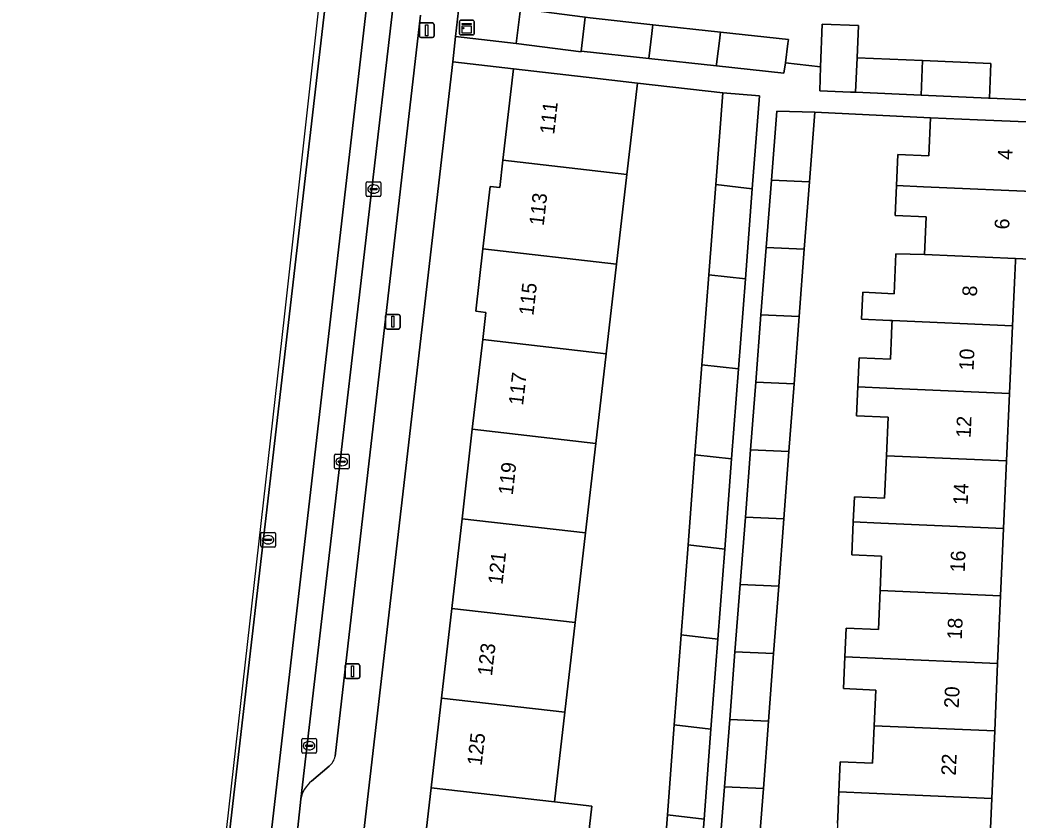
# Model space of a CAD drawing. Extents: x 162250 to 162661, y 380743 to 381606.
# Drawn here: x 162268.3 to 162336.5, y 381046.9 to 381101.5 of the extents above; entities that cross this region are included whole.
import ezdxf

# ---------------------------------------------------------------- set-up
doc = ezdxf.new("R2010")
doc.units = 0
for name, color, linetype in [('IMGEO_Erf', 7, 'Continuous'), ('IMGEO_Kast', 7, 'Continuous'), ('IMGEO_Kolk', 7, 'Continuous'), ('IMGEO_Lichtmast', 7, 'Continuous'), ('IMGEO_Pand', 7, 'Continuous'), ('IMGEO_Pand_nummerreeks', 7, 'Continuous'), ('IMGEO_Parkeervlak_open', 7, 'Continuous'), ('IMGEO_Rijbaan_lokaal_gesloten', 7, 'Continuous'), ('IMGEO_Rioolput', 7, 'Continuous'), ('IMGEO_Voetpad_open', 7, 'Continuous')]:
    doc.layers.add(name, color=color, linetype=linetype)

msp = doc.modelspace()

# ---------------------------------------------------------------- linework, layer by layer
at = {"layer": 'IMGEO_Erf'}
msp.add_lwpolyline([(162341.565, 381113.994), (162300.19, 381118.786), (162298.069, 381100.412), (162302.196, 381099.936), (162302.502, 381102.301), (162306.912, 381101.731), (162307.261, 381101.686), (162311.531, 381101.218), (162316.15, 381100.712), (162320.788, 381100.203), (162320.754, 381099.942), (162320.583, 381098.618), (162322.993, 381098.336), (162323.098, 381101.264), (162325.575, 381101.155), (162325.478, 381098.962), (162329.957, 381098.765), (162334.625, 381098.559), (162334.521, 381096.197), (162340.767, 381095.921)], close=True, dxfattribs=at)
for points in [[(162295.685, 381042.988), (162296.39, 381049.11), (162297.096, 381055.232), (162297.801, 381061.354), (162298.507, 381067.476), (162299.212, 381073.598), (162299.918, 381079.72), (162300.131, 381081.572), (162299.44, 381081.652), (162299.932, 381085.921), (162300.422, 381090.175), (162301.083, 381090.099), (162301.298, 381091.967), (162302.017, 381098.208), (162297.87, 381098.686), (162285.829, 380994.375)], [(162312.06, 381041.1), (162312.531, 381047.249), (162313.002, 381053.398), (162313.472, 381059.548), (162313.943, 381065.696), (162314.414, 381071.845), (162314.885, 381077.995), (162315.356, 381084.144), (162315.827, 381090.293), (162316.307, 381096.56), (162310.485, 381097.232), (162309.766, 381090.991), (162309.06, 381084.869), (162308.355, 381078.747), (162307.649, 381072.625), (162306.943, 381066.503), (162306.238, 381060.381), (162305.532, 381054.259), (162304.827, 381048.137), (162307.374, 381047.844), (162306.668, 381041.722)], [(162324.153, 381046.694), (162324.169, 381047.067), (162324.247, 381048.83), (162324.337, 381050.884), (162326.542, 381050.787), (162326.654, 381053.343), (162326.761, 381055.776), (162324.549, 381055.873), (162324.645, 381058.052), (162324.731, 381060.002), (162326.937, 381059.905), (162327.054, 381062.565), (162327.158, 381064.916), (162325.126, 381065.006), (162325.225, 381067.264), (162325.301, 381068.982), (162327.356, 381068.891), (162327.483, 381071.784), (162327.599, 381074.413), (162325.447, 381074.508), (162325.534, 381076.488), (162325.621, 381078.467), (162327.753, 381078.374), (162327.828, 381080.068), (162327.856, 381080.717), (162327.869, 381081.005), (162327.721, 381081.011), (162325.787, 381081.096), (162325.868, 381082.941), (162328.005, 381082.846), (162328.125, 381085.575), (162330.088, 381085.526), (162330.201, 381088.097), (162328.092, 381088.19), (162328.181, 381090.229), (162328.274, 381092.345), (162330.388, 381092.252), (162330.503, 381094.867), (162322.586, 381095.235), (162322.226, 381090.491), (162321.877, 381085.887), (162321.527, 381081.284), (162321.178, 381076.68), (162320.829, 381072.076), (162320.479, 381067.473), (162320.13, 381062.869), (162319.78, 381058.266), (162319.431, 381053.661), (162319.081, 381049.058), (162318.732, 381044.454)], [(162338.294, 381085.165), (162336.297, 381085.253), (162336.29, 381085.1), (162336.246, 381084.098), (162336.094, 381080.643), (162335.891, 381076.033), (162335.688, 381071.423), (162335.485, 381066.813), (162335.282, 381062.202), (162335.079, 381057.592), (162334.877, 381052.982), (162334.674, 381048.372), (162334.471, 381043.762)]]:
    msp.add_lwpolyline(points, dxfattribs=at)
at = {"layer": 'IMGEO_Kast'}
for p, q in [((162298.332, 381100.593), (162298.332, 381101.434)), ((162298.332, 381101.434), (162298.332, 381100.593)), ((162298.407, 381101.518), (162299.248, 381101.518)), ((162299.248, 381101.518), (162298.407, 381101.518)), ((162299.332, 381101.443), (162299.332, 381100.602)), ((162299.332, 381100.602), (162299.332, 381101.443)), ((162299.257, 381100.518), (162298.416, 381100.518)), ((162298.416, 381100.518), (162299.257, 381100.518))]:
    msp.add_line(p, q, dxfattribs=at)
for points in [[(162298.527, 381101.308), (162299.127, 381101.308), (162299.127, 381101.223), (162298.527, 381101.223), (162298.527, 381101.308)], [(162298.527, 381101.133), (162299.127, 381101.133), (162299.127, 381100.644), (162298.527, 381100.644), (162298.527, 381101.133)]]:
    msp.add_lwpolyline(points, dxfattribs=at)
msp.add_circle((162298.611, 381100.982), 0.0377, dxfattribs=at)
for centre, start, end in [((162298.41, 381101.44), 92.4484, 184.28452), ((162298.41, 381101.44), 92.4484, 184.28452), ((162299.254, 381101.44), 2.4484, 94.28452), ((162299.254, 381101.44), 2.4484, 94.28452), ((162298.41, 381100.596), 182.4484, 274.28452), ((162298.41, 381100.596), 182.4484, 274.28452), ((162299.254, 381100.596), 272.4484, 4.28452), ((162299.254, 381100.596), 272.4484, 4.28452)]:
    msp.add_arc(centre, 0.0779, start, end, dxfattribs=at)
at = {"layer": 'IMGEO_Kolk'}
for p, q in [((162292.047, 381090.491), (162292.899, 381090.491)), ((162291.972, 381089.565), (162291.972, 381090.417)), ((162292.231, 381089.985), (162292.231, 381089.997)), ((162292.669, 381089.948), (162292.271, 381089.948)), ((162292.274, 381090.034), (162292.672, 381090.034)), ((162292.46, 381090.271), (162292.485, 381090.271)), ((162292.715, 381089.997), (162292.715, 381089.985)), ((162292.973, 381090.417), (162292.973, 381089.565)), ((162292.899, 381089.491), (162292.047, 381089.491)), ((162292.483, 381089.711), (162292.458, 381089.711)), ((162289.794, 381070.95), (162289.794, 381071.802)), ((162289.869, 381071.876), (162290.721, 381071.876)), ((162290.096, 381071.419), (162290.494, 381071.419)), ((162290.282, 381071.656), (162290.307, 381071.656)), ((162290.795, 381071.802), (162290.795, 381070.95)), ((162290.721, 381070.876), (162289.869, 381070.876)), ((162290.053, 381071.37), (162290.053, 381071.382)), ((162290.491, 381071.333), (162290.093, 381071.333)), ((162290.305, 381071.096), (162290.28, 381071.096)), ((162290.537, 381071.382), (162290.537, 381071.37)), ((162287.561, 381051.549), (162287.561, 381052.401)), ((162287.636, 381052.475), (162288.488, 381052.475)), ((162288.562, 381052.401), (162288.562, 381051.549)), ((162287.82, 381051.969), (162287.82, 381051.981)), ((162288.258, 381051.932), (162287.86, 381051.932)), ((162287.863, 381052.018), (162288.261, 381052.018)), ((162288.072, 381051.695), (162288.047, 381051.695)), ((162288.049, 381052.255), (162288.074, 381052.255)), ((162288.304, 381051.981), (162288.304, 381051.969)), ((162288.488, 381051.475), (162287.636, 381051.475))]:
    msp.add_line(p, q, dxfattribs=at)
for points in [[(162292.047, 381090.491), (162292.899, 381090.491)], [(162291.972, 381089.565), (162291.972, 381090.417)], [(162292.973, 381090.417), (162292.973, 381089.565)], [(162292.899, 381089.491), (162292.047, 381089.491)], [(162289.794, 381070.95), (162289.794, 381071.802)], [(162289.869, 381071.876), (162290.721, 381071.876)], [(162290.795, 381071.802), (162290.795, 381070.95)], [(162290.721, 381070.876), (162289.869, 381070.876)], [(162287.561, 381051.549), (162287.561, 381052.401)], [(162287.636, 381052.475), (162288.488, 381052.475)], [(162288.562, 381052.401), (162288.562, 381051.549)], [(162288.488, 381051.475), (162287.636, 381051.475)]]:
    msp.add_lwpolyline(points, dxfattribs=at)
for centre, radius, start, end in [((162292.049, 381090.415), 0.0765, 91.55205, 178.44795), ((162292.049, 381090.415), 0.0765, 91.55205, 178.44795), ((162292.897, 381090.415), 0.0765, 1.55205, 88.44795), ((162292.897, 381090.415), 0.0765, 1.55205, 88.44795), ((162292.271, 381089.994), 0.0403, 85.87752, 175.75265), ((162292.268, 381089.984), 0.0366, 178.93798, 274.71019), ((162292.672, 381089.991), 0.043, 264.86636, 352.45326), ((162292.676, 381089.996), 0.0386, 1.73085, 96.63898), ((162292.049, 381089.567), 0.0765, 181.55205, 268.44795), ((162292.049, 381089.567), 0.0765, 181.55205, 268.44795), ((162292.897, 381089.567), 0.0765, 271.55205, 358.44795), ((162292.897, 381089.567), 0.0765, 271.55205, 358.44795), ((162289.871, 381071.8), 0.0765, 91.55205, 178.44795), ((162289.871, 381071.8), 0.0765, 91.55205, 178.44795), ((162290.093, 381071.379), 0.0403, 85.87752, 175.75265), ((162290.498, 381071.381), 0.0386, 1.73085, 96.63898), ((162290.719, 381071.8), 0.0765, 1.55205, 88.44795), ((162290.719, 381071.8), 0.0765, 1.55205, 88.44795), ((162289.871, 381070.952), 0.0765, 181.55205, 268.44795), ((162289.871, 381070.952), 0.0765, 181.55205, 268.44795), ((162290.09, 381071.369), 0.0366, 178.93798, 274.71019), ((162290.494, 381071.376), 0.043, 264.86636, 352.45326), ((162290.719, 381070.952), 0.0765, 271.55205, 358.44795), ((162290.719, 381070.952), 0.0765, 271.55205, 358.44795), ((162287.638, 381052.399), 0.0765, 91.55205, 178.44795), ((162287.638, 381052.399), 0.0765, 91.55205, 178.44795), ((162288.486, 381052.399), 0.0765, 1.55205, 88.44795), ((162288.486, 381052.399), 0.0765, 1.55205, 88.44795), ((162287.86, 381051.978), 0.0403, 85.87752, 175.75265), ((162287.857, 381051.968), 0.0366, 178.93798, 274.71019), ((162288.261, 381051.975), 0.043, 264.86636, 352.45326), ((162288.265, 381051.98), 0.0386, 1.73085, 96.63898), ((162287.638, 381051.551), 0.0765, 181.55205, 268.44795), ((162287.638, 381051.551), 0.0765, 181.55205, 268.44795), ((162288.486, 381051.551), 0.0765, 271.55205, 358.44795), ((162288.486, 381051.551), 0.0765, 271.55205, 358.44795)]:
    msp.add_arc(centre, radius, start, end, dxfattribs=at)
for centre, major_axis, ratio, start_param, end_param in [((162292.459, 381089.991), (-0.387, 0.002), 0.722429, 4.712389, 7.853982), ((162292.484, 381089.991), (-0.39, 0.002), 0.717154, 1.570796, 4.712389), ((162290.281, 381071.376), (-0.387, 0.002), 0.722429, 4.712389, 7.853982), ((162290.306, 381071.376), (-0.39, 0.002), 0.717154, 1.570796, 4.712389), ((162288.048, 381051.975), (-0.387, 0.002), 0.722429, 4.712389, 7.853982), ((162288.073, 381051.975), (-0.39, 0.002), 0.717154, 1.570796, 4.712389)]:
    msp.add_ellipse(centre, major_axis=major_axis, ratio=ratio, start_param=start_param, end_param=end_param, dxfattribs=at)
at = {"layer": 'IMGEO_Lichtmast'}
for p, q in [((162295.605, 381100.438), (162295.605, 381101.238)), ((162295.605, 381101.238), (162295.605, 381100.438)), ((162295.705, 381101.338), (162296.495, 381101.338)), ((162296.495, 381101.338), (162295.705, 381101.338)), ((162296.595, 381101.238), (162296.595, 381100.438)), ((162296.595, 381100.438), (162296.595, 381101.238)), ((162296.495, 381100.338), (162295.705, 381100.338)), ((162295.705, 381100.338), (162296.495, 381100.338)), ((162293.287, 381080.529), (162293.287, 381081.329)), ((162293.287, 381081.329), (162293.287, 381080.529)), ((162293.387, 381081.429), (162294.177, 381081.429)), ((162294.177, 381081.429), (162293.387, 381081.429)), ((162294.277, 381081.329), (162294.277, 381080.529)), ((162294.277, 381080.529), (162294.277, 381081.329)), ((162294.177, 381080.429), (162293.387, 381080.429)), ((162293.387, 381080.429), (162294.177, 381080.429)), ((162290.531, 381056.662), (162290.531, 381057.462)), ((162290.531, 381057.462), (162290.531, 381056.662)), ((162290.631, 381057.562), (162291.421, 381057.562)), ((162291.421, 381057.562), (162290.631, 381057.562)), ((162291.521, 381057.462), (162291.521, 381056.662)), ((162291.521, 381056.662), (162291.521, 381057.462)), ((162291.421, 381056.562), (162290.631, 381056.562)), ((162290.631, 381056.562), (162291.421, 381056.562))]:
    msp.add_line(p, q, dxfattribs=at)
for points in [[(162296.025, 381101.213), (162296.175, 381101.213), (162296.175, 381100.463), (162296.025, 381100.463), (162296.025, 381101.213)], [(162293.707, 381081.304), (162293.857, 381081.304), (162293.857, 381080.554), (162293.707, 381080.554), (162293.707, 381081.304)], [(162290.951, 381057.437), (162291.101, 381057.437), (162291.101, 381056.687), (162290.951, 381056.687), (162290.951, 381057.437)]]:
    msp.add_lwpolyline(points, dxfattribs=at)
for centre, start, end in [((162295.705, 381101.238), 90, 180), ((162295.705, 381101.238), 90, 180), ((162296.495, 381101.238), 0, 90), ((162296.495, 381101.238), 360, 90), ((162295.705, 381100.438), 180, 270), ((162295.705, 381100.438), 180, 270), ((162296.495, 381100.438), 270, 0), ((162296.495, 381100.438), 270, 0), ((162293.387, 381081.329), 90, 180), ((162293.387, 381081.329), 90, 180), ((162294.177, 381081.329), 0, 90), ((162294.177, 381081.329), 360, 90), ((162293.387, 381080.529), 180, 270), ((162293.387, 381080.529), 180, 270), ((162294.177, 381080.529), 270, 0), ((162294.177, 381080.529), 270, 0), ((162290.631, 381057.462), 90, 180), ((162290.631, 381057.462), 90, 180), ((162291.421, 381057.462), 0, 90), ((162291.421, 381057.462), 360, 90), ((162290.631, 381056.662), 180, 270), ((162290.631, 381056.662), 180, 270), ((162291.421, 381056.662), 270, 0), ((162291.421, 381056.662), 270, 0)]:
    msp.add_arc(centre, 0.1, start, end, dxfattribs=at)
at = {"layer": 'IMGEO_Pand'}
for points in [[(162306.912, 381101.731), (162302.502, 381102.301), (162302.196, 381099.936), (162306.634, 381099.362), (162306.641, 381099.418)], [(162311.531, 381101.218), (162307.261, 381101.686), (162306.912, 381101.731), (162306.641, 381099.418), (162311.26, 381098.913), (162311.46, 381100.618), (162311.508, 381101.021)], [(162316.15, 381100.712), (162311.531, 381101.218), (162311.508, 381101.021), (162311.46, 381100.618), (162311.26, 381098.913), (162315.88, 381098.407), (162315.893, 381098.517), (162316.101, 381100.295), (162316.13, 381100.54)], [(162316.15, 381100.712), (162316.13, 381100.54), (162316.101, 381100.295), (162315.893, 381098.517), (162315.88, 381098.407), (162320.49, 381097.901), (162320.583, 381098.618), (162320.754, 381099.942), (162320.788, 381100.203)], [(162325.575, 381101.155), (162323.098, 381101.264), (162322.993, 381098.336), (162322.934, 381096.707), (162325.027, 381096.615), (162325.374, 381096.6), (162325.478, 381098.962)], [(162329.957, 381098.765), (162325.478, 381098.962), (162325.374, 381096.6), (162329.853, 381096.402)], [(162334.625, 381098.559), (162329.957, 381098.765), (162329.853, 381096.402), (162334.463, 381096.199), (162334.521, 381096.197)], [(162309.766, 381090.991), (162310.485, 381097.232), (162306.985, 381097.635), (162302.017, 381098.208), (162301.298, 381091.967)], [(162315.827, 381090.293), (162318.328, 381090.005), (162318.815, 381096.367), (162316.307, 381096.56)], [(162319.633, 381090.605), (162322.226, 381090.491), (162322.586, 381095.235), (162319.997, 381095.302)], [(162338.497, 381089.775), (162338.705, 381094.506), (162333.71, 381094.726), (162330.503, 381094.867), (162330.388, 381092.252), (162328.274, 381092.345), (162328.181, 381090.229), (162330.02, 381090.148)], [(162299.932, 381085.921), (162309.06, 381084.869), (162309.766, 381090.991), (162301.298, 381091.967), (162301.083, 381090.099), (162300.422, 381090.175)], [(162319.633, 381090.605), (162319.277, 381086.002), (162321.877, 381085.887), (162322.226, 381090.491)], [(162315.827, 381090.293), (162315.356, 381084.144), (162317.857, 381083.856), (162318.328, 381090.005)], [(162338.497, 381089.775), (162330.02, 381090.148), (162328.181, 381090.229), (162328.092, 381088.19), (162330.201, 381088.097), (162330.088, 381085.526), (162336.297, 381085.253), (162338.294, 381085.165)], [(162299.932, 381085.921), (162299.44, 381081.652), (162300.131, 381081.572), (162299.918, 381079.72), (162308.355, 381078.747), (162309.06, 381084.869)], [(162321.527, 381081.284), (162321.877, 381085.887), (162319.277, 381086.002), (162318.921, 381081.398)], [(162336.297, 381085.253), (162330.088, 381085.526), (162328.125, 381085.575), (162328.005, 381082.846), (162325.868, 381082.941), (162325.787, 381081.096), (162327.721, 381081.011), (162327.869, 381081.005), (162336.094, 381080.643), (162336.246, 381084.098), (162336.29, 381085.1)], [(162317.386, 381077.706), (162317.857, 381083.856), (162315.356, 381084.144), (162314.885, 381077.995)], [(162318.566, 381076.795), (162321.178, 381076.68), (162321.527, 381081.284), (162318.921, 381081.398)], [(162336.094, 381080.643), (162327.869, 381081.005), (162327.856, 381080.717), (162327.828, 381080.068), (162327.753, 381078.374), (162325.621, 381078.467), (162325.534, 381076.488), (162327.518, 381076.401), (162335.891, 381076.033)], [(162299.212, 381073.598), (162307.649, 381072.625), (162308.355, 381078.747), (162299.918, 381079.72)], [(162314.414, 381071.845), (162316.915, 381071.557), (162317.386, 381077.706), (162314.885, 381077.995)], [(162318.566, 381076.795), (162318.21, 381072.191), (162320.829, 381072.076), (162321.178, 381076.68)], [(162335.688, 381071.423), (162335.891, 381076.033), (162327.518, 381076.401), (162325.534, 381076.488), (162325.447, 381074.508), (162327.599, 381074.413), (162327.483, 381071.784)], [(162306.943, 381066.503), (162307.649, 381072.625), (162299.212, 381073.598), (162298.507, 381067.476)], [(162318.21, 381072.191), (162317.854, 381067.589), (162320.479, 381067.473), (162320.829, 381072.076)], [(162314.414, 381071.845), (162313.943, 381065.696), (162316.444, 381065.408), (162316.915, 381071.557)], [(162335.485, 381066.813), (162335.688, 381071.423), (162327.483, 381071.784), (162327.356, 381068.891), (162325.301, 381068.982), (162325.225, 381067.264), (162327.112, 381067.181)], [(162306.238, 381060.381), (162306.943, 381066.503), (162298.507, 381067.476), (162297.801, 381061.354)], [(162317.498, 381062.984), (162320.13, 381062.869), (162320.479, 381067.473), (162317.854, 381067.589)], [(162335.485, 381066.813), (162327.112, 381067.181), (162325.225, 381067.264), (162325.126, 381065.006), (162327.158, 381064.916), (162327.054, 381062.565), (162335.282, 381062.202)], [(162313.943, 381065.696), (162313.472, 381059.548), (162315.973, 381059.26), (162316.444, 381065.408)], [(162317.498, 381062.984), (162317.142, 381058.382), (162319.78, 381058.266), (162320.13, 381062.869)], [(162324.645, 381058.052), (162326.706, 381057.961), (162335.079, 381057.592), (162335.282, 381062.202), (162327.054, 381062.565), (162326.937, 381059.905), (162324.731, 381060.002)], [(162297.096, 381055.232), (162305.532, 381054.259), (162306.238, 381060.381), (162297.801, 381061.354)], [(162315.502, 381053.11), (162315.973, 381059.26), (162313.472, 381059.548), (162313.002, 381053.398)], [(162319.431, 381053.661), (162319.78, 381058.266), (162317.142, 381058.382), (162316.786, 381053.777)], [(162324.645, 381058.052), (162324.549, 381055.873), (162326.761, 381055.776), (162326.654, 381053.343), (162334.877, 381052.982), (162335.079, 381057.592), (162326.706, 381057.961)], [(162297.096, 381055.232), (162296.39, 381049.11), (162304.827, 381048.137), (162305.532, 381054.259)], [(162319.431, 381053.661), (162316.786, 381053.777), (162316.43, 381049.175), (162319.081, 381049.058)], [(162315.502, 381053.11), (162313.002, 381053.398), (162312.531, 381047.249), (162315.032, 381046.961)], [(162334.674, 381048.372), (162334.877, 381052.982), (162326.654, 381053.343), (162326.542, 381050.787), (162324.337, 381050.884), (162324.247, 381048.83), (162326.3, 381048.74)], [(162295.685, 381042.988), (162304.121, 381042.015), (162306.668, 381041.722), (162307.374, 381047.844), (162304.827, 381048.137), (162296.39, 381049.11)], [(162319.081, 381049.058), (162316.43, 381049.175), (162316.074, 381044.571), (162318.732, 381044.454)], [(162334.674, 381048.372), (162326.3, 381048.74), (162324.247, 381048.83), (162324.169, 381047.067), (162324.153, 381046.694), (162324.044, 381044.22), (162326.278, 381044.122), (162334.471, 381043.762)], [(162314.561, 381040.812), (162315.032, 381046.961), (162312.531, 381047.249), (162312.06, 381041.1)]]:
    msp.add_lwpolyline(points, close=True, dxfattribs=at)
at = {"layer": 'IMGEO_Parkeervlak_open'}
for points in [[(162294.122, 381105.302), (162287.512, 381048.327)], [(162289.85, 381051.252), (162295.67, 381101.867)], [(162288.239, 381049.564), (162289.436, 381050.569)]]:
    msp.add_lwpolyline(points, dxfattribs=at)
for centre, radius, start, end in [((162288.612, 381051.536), 1.27, 310.4561, 347.09966), ((162289.415, 381048.041), 1.924, 127.66511, 171.44835)]:
    msp.add_arc(centre, radius, start, end, dxfattribs=at)
at = {"layer": 'IMGEO_Rijbaan_lokaal_gesloten'}
msp.add_lwpolyline([(162268.325, 380921.495), (162271.149, 380921.172), (162275.659, 380960.888), (162277.356, 380960.724), (162278.069, 380966.836), (162278.655, 380972.068), (162279.19, 380976.722), (162279.196, 380976.775), (162279.203, 380976.84), (162277.507, 380977.016), (162278.556, 380986.022), (162293.089, 381111.897), (162290.278, 381112.181), (162274.701, 380977.591), (162274.657, 380977.597), (162268.325, 380921.495)], dxfattribs=at)
for points in [[(162274.657, 380977.597), (162274.701, 380977.591), (162290.278, 381112.181), (162290.005, 381112.208), (162289.809, 381112.228), (162286.357, 381081.269), (162276.732, 380995.981)], [(162294.788, 381111.726), (162293.261, 381111.88), (162293.089, 381111.897), (162278.556, 380986.022), (162277.507, 380977.016), (162279.203, 380976.84), (162279.928, 380983.133), (162281.338, 380995.138), (162281.526, 380996.953), (162287.288, 381046.38), (162287.512, 381048.327), (162294.122, 381105.302), (162294.331, 381107.316)]]:
    msp.add_lwpolyline(points, close=True, dxfattribs=at)
at = {"layer": 'IMGEO_Rioolput'}
for p, q in [((162284.767, 381065.616), (162284.767, 381066.468)), ((162284.842, 381066.542), (162285.694, 381066.542)), ((162285.026, 381066.036), (162285.026, 381066.048)), ((162285.464, 381065.999), (162285.066, 381065.999)), ((162285.069, 381066.085), (162285.467, 381066.085)), ((162285.255, 381066.322), (162285.28, 381066.322)), ((162285.51, 381066.048), (162285.51, 381066.036)), ((162285.768, 381066.468), (162285.768, 381065.616)), ((162285.694, 381065.542), (162284.842, 381065.542)), ((162285.278, 381065.762), (162285.253, 381065.762))]:
    msp.add_line(p, q, dxfattribs=at)
for points in [[(162284.767, 381065.616), (162284.767, 381066.468)], [(162284.842, 381066.542), (162285.694, 381066.542)], [(162285.768, 381066.468), (162285.768, 381065.616)], [(162285.694, 381065.542), (162284.842, 381065.542)]]:
    msp.add_lwpolyline(points, dxfattribs=at)
for centre, radius, start, end in [((162284.844, 381066.466), 0.0765, 91.55205, 178.44795), ((162284.844, 381066.466), 0.0765, 91.55205, 178.44795), ((162285.066, 381066.045), 0.0403, 85.87752, 175.75265), ((162285.063, 381066.035), 0.0366, 178.93798, 274.71019), ((162285.467, 381066.042), 0.043, 264.86636, 352.45326), ((162285.471, 381066.047), 0.0386, 1.73085, 96.63898), ((162285.692, 381066.466), 0.0765, 1.55205, 88.44795), ((162285.692, 381066.466), 0.0765, 1.55205, 88.44795), ((162284.844, 381065.618), 0.0765, 181.55205, 268.44795), ((162284.844, 381065.618), 0.0765, 181.55205, 268.44795), ((162285.692, 381065.618), 0.0765, 271.55205, 358.44795), ((162285.692, 381065.618), 0.0765, 271.55205, 358.44795)]:
    msp.add_arc(centre, radius, start, end, dxfattribs=at)
for centre, major_axis, ratio, start_param, end_param in [((162285.254, 381066.042), (-0.387, 0.002), 0.722429, 4.712389, 7.853982), ((162285.279, 381066.042), (-0.39, 0.002), 0.717154, 1.570796, 4.712389)]:
    msp.add_ellipse(centre, major_axis=major_axis, ratio=ratio, start_param=start_param, end_param=end_param, dxfattribs=at)
at = {"layer": 'IMGEO_Voetpad_open'}
for points in [[(162282.368, 380964.496), (162282.665, 380967.703), (162283.032, 380971.129), (162283.298, 380972.915), (162283.492, 380974.216), (162283.759, 380976.44), (162285.702, 380993.275), (162285.829, 380994.375), (162297.87, 381098.686), (162298.069, 381100.412), (162300.19, 381118.786), (162300.393, 381121.029)], [(162295.67, 381101.867), (162289.85, 381051.252)], [(162340.767, 381095.921), (162334.521, 381096.197), (162334.463, 381096.199), (162329.853, 381096.402), (162325.374, 381096.6), (162325.027, 381096.615), (162322.934, 381096.707), (162322.993, 381098.336), (162320.583, 381098.618), (162320.49, 381097.901), (162315.88, 381098.407), (162311.26, 381098.913), (162306.641, 381099.418), (162306.634, 381099.362), (162302.196, 381099.936), (162298.069, 381100.412), (162297.87, 381098.686), (162302.017, 381098.208), (162306.985, 381097.635), (162310.485, 381097.232), (162316.307, 381096.56), (162318.815, 381096.367), (162318.328, 381090.005), (162317.857, 381083.856), (162317.386, 381077.706), (162316.915, 381071.557), (162316.444, 381065.408), (162315.973, 381059.26), (162315.502, 381053.11), (162315.032, 381046.961), (162314.561, 381040.812)], [(162316.074, 381044.571), (162316.43, 381049.175), (162316.786, 381053.777), (162317.142, 381058.382), (162317.498, 381062.984), (162317.854, 381067.589), (162318.21, 381072.191), (162318.566, 381076.795), (162318.921, 381081.398), (162319.277, 381086.002), (162319.633, 381090.605), (162319.997, 381095.302), (162322.586, 381095.235), (162330.503, 381094.867), (162333.71, 381094.726), (162338.705, 381094.506)], [(162289.436, 381050.569), (162288.239, 381049.564)], [(162287.512, 381048.327), (162287.288, 381046.38)]]:
    msp.add_lwpolyline(points, dxfattribs=at)
for centre, radius, start, end in [((162288.612, 381051.536), 1.27, 310.4561, 347.09966), ((162289.415, 381048.041), 1.924, 127.66511, 171.44835)]:
    msp.add_arc(centre, radius, start, end, dxfattribs=at)

# ---------------------------------------------------------------- texts
at = {"layer": 'IMGEO_Pand_nummerreeks'}
for s, rotation, p in [('111', 83.44716, (162304.8, 381093.694)), ('4', 87.47902, (162336.071, 381091.969)), ('113', 83.44716, (162304.083, 381087.451)), ('6', 87.4792, (162335.862, 381087.222)), ('115', 83.44716, (162303.378, 381081.32)), ('8', 87.4792, (162333.66, 381082.643)), ('10', 87.4792, (162333.436, 381077.586)), ('117', 83.44716, (162302.674, 381075.19)), ('12', 87.48029, (162333.234, 381072.986)), ('119', 83.44716, (162301.97, 381069.059)), ('14', 87.48029, (162333.032, 381068.394)), ('121', 83.44716, (162301.269, 381062.949)), ('16', 87.48029, (162332.83, 381063.799)), ('18', 87.48029, (162332.628, 381059.206)), ('123', 83.44716, (162300.552, 381056.705)), ('20', 87.48029, (162332.421, 381054.52)), ('125', 83.44716, (162299.847, 381050.575)), ('22', 87.48029, (162332.219, 381049.919))]:
    msp.add_text(s, height=1, rotation=rotation, dxfattribs=at).set_placement(p)

doc.saveas('drawing.dxf')
